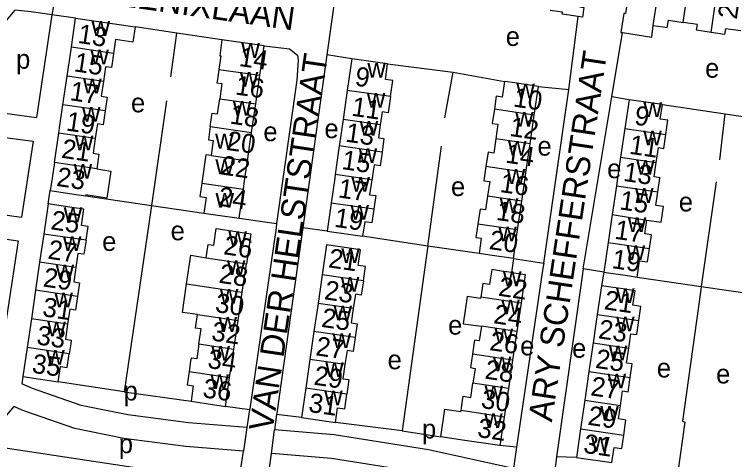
# Model space of a CAD drawing. Extents: x 163012 to 165277, y 382513 to 383987.
# Drawn here: x 163920.9 to 164071.5, y 382941.3 to 383034.2 of the extents above; entities that cross this region are included whole.
import ezdxf

# ---------------------------------------------------------------- set-up
doc = ezdxf.new("R2010")
doc.units = 0
for name, color, linetype in [('BLT_Basislijn', 7, 'Continuous'), ('BLT_Bebouwing', 7, 'Continuous'), ('BLT_Centroide', 7, 'Continuous'), ('BLT_Huisnummer', 7, 'Continuous'), ('BLT_Huisnummer_ tussenligend', 7, 'Continuous'), ('BLT_Onderverdeling_panden', 7, 'Continuous'), ('BLT_Straatnaam', 7, 'Continuous'), ('BLT_Vlakafsluiter', 7, 'Continuous')]:
    doc.layers.add(name, color=color, linetype=linetype)

msp = doc.modelspace()

# ---------------------------------------------------------------- linework, layer by layer
at = {"layer": 'BLT_Basislijn'}
for p, q in [((163933.72, 383033.43), (163928.78, 383034.15)), ((164036.78, 383018.52), (164038.76, 383033.78)), ((163954.91, 383030.33), (163946.16, 383031.61)), ((163953.66, 383021.2), (163954.91, 383030.33)), ((163964.32, 383028.95), (163954.91, 383030.33)), ((164045.79, 383016.99), (164048.02, 383030.43)), ((163986.21, 383025.76), (163981.2, 382989.66)), ((163991.46, 383024.98), (163986.21, 383025.76)), ((163998.93, 383023.9), (164012.67, 383022.18)), ((164010.93, 383012.61), (164012.67, 383022.18)), ((164012.67, 383022.18), (164023.35, 383020.25)), ((164030.48, 383019.21), (164036.78, 383018.52)), ((164031.56, 382982.31), (164036.78, 383018.52)), ((163952.71, 383016.16), (163949.61, 382994.31)), ((164039.84, 382981.1), (164045.79, 383016.99)), ((164049.39, 383016.42), (164045.79, 383016.99)), ((164056.37, 383015.39), (164069.46, 383013.45)), ((163915.9, 383013.98), (163925.56, 383012.72)), ((164068.4, 383003.83), (164069.46, 383013.45)), ((164069.46, 383013.45), (164081.1, 383011.71)), ((163915.17, 383009.03), (163924.82, 383007.78)), ((164007.33, 382985.82), (164010.19, 383006.73)), ((164067.6, 382999.24), (164064.49, 382977.41)), ((163928.01, 382994.65), (163928.43, 382997.43)), ((163935.85, 382996.34), (163949.61, 382994.31)), ((163949.61, 382994.31), (163960.52, 382992.74)), ((163912.83, 382993.19), (163922.44, 382991.91)), ((163967.92, 382991.65), (163975.74, 382990.58)), ((163986.27, 382988.97), (163981.2, 382989.66)), ((163912.1, 382988.25), (163921.69, 382986.96)), ((164007.33, 382985.82), (163993.71, 382987.89)), ((164018.04, 382984.28), (164007.33, 382985.82)), ((164025.22, 382983.23), (164024.81, 382980.34)), ((164025.22, 382983.23), (164031.56, 382982.31)), ((164044.12, 382980.42), (164039.84, 382981.1)), ((164044.12, 382980.42), (164043.65, 382977.56)), ((164051.08, 382979.39), (164064.49, 382977.41)), ((164064.49, 382977.41), (164075.82, 382975.74)), ((163922.7, 382958.59), (163922.48, 382957.11)), ((163943.88, 382955.44), (163930.09, 382957.5)), ((163943.88, 382955.44), (163957.85, 382953.43)), ((163970.07, 382951.64), (163965.04, 382952.37)), ((163970.07, 382951.64), (163969.53, 382947.96)), ((163975.74, 382950.65), (163975.31, 382947.48)), ((163980.93, 382950.04), (163975.74, 382950.65)), ((164001.96, 382947.28), (163988.05, 382949.01)), ((163969.53, 382947.96), (163968.8, 382943)), ((163974.64, 382942.52), (163975.31, 382947.48)), ((164001.96, 382947.28), (164010.03, 382946.03)), ((164025.87, 382943.82), (164022.36, 382944.19)), ((164025.87, 382943.82), (164025.23, 382939.42)), ((163968.18, 382938.94), (163968.8, 382943)), ((163974.01, 382938.04), (163974.64, 382942.52)), ((164034.21, 382941.83), (164033.72, 382937.87)), ((164038.39, 382941.7), (164034.21, 382941.83))]:
    msp.add_line(p, q, dxfattribs=at)
for points in [[(163988.64, 383043.13), (163986.29, 383026.31), (163986.21, 383025.76)], [(163928.78, 383034.15), (163924.42, 383034.78), (163920.99, 383035.12), (163918.78, 383032.49), (163918.5, 383031.62), (163915.9, 383013.98)], [(163928.78, 383034.15), (163925.56, 383012.72)], [(163973.1, 383027.69), (163978.4, 383027.01), (163980.11, 383025.72), (163980.23, 383024.68), (163979.98, 383020.47), (163975.74, 382990.58)], [(163924.82, 383007.78), (163922.44, 382991.91)], [(163949.61, 382994.31), (163949.47, 382993.33), (163943.88, 382955.44)], [(163975.74, 382990.58), (163975.61, 382989.65), (163970.11, 382951.89), (163970.07, 382951.64)], [(163981.2, 382989.66), (163981.07, 382988.73), (163975.77, 382950.92), (163975.74, 382950.65)], [(163921.69, 382986.96), (163918.94, 382968.59)], [(164007.33, 382985.82), (164007.21, 382984.96), (164001.96, 382947.28)], [(164031.56, 382982.31), (164031.41, 382981.22), (164025.87, 382943.82)], [(164039.84, 382981.1), (164039.58, 382979.58), (164034.21, 382941.83)], [(164064.49, 382977.41), (164064.32, 382976.22), (164060.57, 382949.27), (164061.03, 382949.04), (164059.62, 382938.6)], [(163969.53, 382947.96), (163957.3, 382948.96), (163944.65, 382950.6), (163934.91, 382952.57), (163924.74, 382956.08), (163922.48, 382957.11)], [(163968.8, 382943), (163956.77, 382943.99), (163943.83, 382945.66), (163933.59, 382947.74), (163922.89, 382951.43), (163920.84, 382952.36), (163914.82, 382945.41)], [(164025.23, 382939.42), (164007.45, 382943.3), (163987.8, 382946.46), (163975.31, 382947.48)], [(163918.6, 382943.79), (163957.28, 382937.97)], [(164024.5, 382934.46), (164006.52, 382938.39), (163987.2, 382941.49), (163974.64, 382942.52)]]:
    msp.add_lwpolyline(points, dxfattribs=at)
at = {"layer": 'BLT_Bebouwing'}
for p, q in [((163932.83, 383027.36), (163933.72, 383033.43)), ((163933.72, 383033.43), (163946.16, 383031.61)), ((163973.1, 383027.69), (163964.32, 383028.95)), ((163931.95, 383021.34), (163932.83, 383027.36)), ((163972.22, 383021.54), (163973.1, 383027.69)), ((163991.46, 383024.98), (163990.5, 383018.36)), ((163931.07, 383015.38), (163931.95, 383021.34)), ((163971.36, 383015.55), (163972.22, 383021.54)), ((164029.6, 383013.21), (164030.48, 383019.21)), ((163990.5, 383018.36), (163989.63, 383012.3)), ((164049.39, 383016.42), (164048.51, 383010.42)), ((163970.5, 383009.58), (163971.36, 383015.55)), ((164028.73, 383007.22), (164029.6, 383013.21)), ((164048.51, 383010.42), (164047.63, 383004.42)), ((163929.31, 383003.33), (163930.2, 383009.42)), ((164027.85, 383001.22), (164028.73, 383007.22)), ((163988.82, 383006.75), (163987.96, 383000.81)), ((164046.75, 382998.42), (164045.88, 382992.42)), ((163967.92, 382991.65), (163968.8, 382997.74)), ((164026.1, 382989.23), (164026.98, 382995.22)), ((163928.01, 382994.65), (163927.08, 382988.35)), ((163987.13, 382994.84), (163986.27, 382988.97)), ((164045.88, 382992.42), (164045.03, 382986.63)), ((164025.22, 382983.23), (164026.1, 382989.23)), ((163927.08, 382988.35), (163926.21, 382982.46)), ((164045.03, 382986.63), (164044.12, 382980.42)), ((163926.21, 382982.46), (163925.36, 382976.62)), ((163968.55, 382976.23), (163969.42, 382982.17)), ((163985.26, 382979.84), (163984.39, 382973.87)), ((164043.65, 382977.56), (164042.77, 382971.59)), ((163925.36, 382976.62), (163924.47, 382970.64)), ((163967.68, 382970.3), (163968.55, 382976.23)), ((163984.39, 382973.87), (163983.54, 382967.99)), ((164026.83, 382973.96), (164025.94, 382968)), ((164042.77, 382971.59), (164041.9, 382965.62)), ((163924.47, 382970.64), (163923.59, 382964.64)), ((163966.8, 382964.34), (163967.68, 382970.3)), ((163983.54, 382967.99), (163982.69, 382962.16)), ((164025.94, 382968), (164025.05, 382962.05)), ((164041.9, 382965.62), (164041.02, 382959.65)), ((163923.59, 382964.64), (163922.7, 382958.59)), ((163965.92, 382958.41), (163966.8, 382964.34)), ((163982.69, 382962.16), (163981.82, 382956.16)), ((164025.05, 382962.05), (164024.17, 382956.09)), ((164041.02, 382959.65), (164040.14, 382953.68)), ((163922.7, 382958.59), (163930.09, 382957.5)), ((163965.04, 382952.37), (163965.92, 382958.41)), ((163981.82, 382956.16), (163980.93, 382950.04)), ((164024.17, 382956.09), (164023.28, 382950.14)), ((163957.85, 382953.43), (163965.04, 382952.37)), ((164040.14, 382953.68), (164039.27, 382947.71)), ((163980.93, 382950.04), (163988.05, 382949.01)), ((164023.28, 382950.14), (164022.36, 382944.19)), ((164039.27, 382947.71), (164038.39, 382941.7)), ((164038.39, 382941.7), (164045.81, 382940.64))]:
    msp.add_line(p, q, dxfattribs=at)
for points in [[(164040.16, 383043.22), (164039.09, 383035.8), (164039.95, 383035.67), (164039.65, 383033.65), (164038.76, 383033.78)], [(164049.79, 383041.81), (164048.68, 383034.4), (164048.3, 383034.45), (164047.7, 383030.48), (164048.02, 383030.43)], [(164038.76, 383033.78), (164035.42, 383034.26), (164035.48, 383034.7), (164032.9, 383035.08)], [(164054.45, 383031.92), (164056.52, 383031.61), (164057.4, 383031.47), (164057.63, 383033.02), (164060.7, 383032.56)], [(164066.54, 383030.45), (164063.52, 383030.91), (164063.7, 383032.11), (164060.7, 383032.56)], [(163946.16, 383031.61), (163945.69, 383028.43), (163942.07, 383029), (163941.64, 383026.06)], [(164048.02, 383030.43), (164054.13, 383029.51), (164054.45, 383031.92)], [(164072.74, 383030.77), (164069.55, 383031.24), (164069.37, 383030.03), (164066.54, 383030.45)], [(163964.32, 383028.95), (163963.84, 383025.61), (163964.07, 383025.57), (163963.66, 383022.76)], [(163941.64, 383026.06), (163941.35, 383024.05), (163941.21, 383023.12), (163939.98, 383023.31), (163939.53, 383020.23)], [(163998.93, 383023.9), (163996.41, 383024.26), (163991.46, 383024.98)], [(163999.51, 383017.06), (164000, 383020.41), (163998.46, 383020.64), (163998.93, 383023.9)], [(163963.66, 383022.76), (163963.36, 383020.62), (163963.26, 383019.96), (163964.31, 383019.81), (163963.85, 383016.62)], [(163939.53, 383020.23), (163939.08, 383017.16), (163940.31, 383016.98), (163939.88, 383014.08)], [(164023.35, 383020.25), (164022.87, 383016.96), (164021.64, 383017.14), (164021.25, 383014.43)], [(164030.48, 383019.21), (164025.53, 383019.93), (164023.35, 383020.25)], [(163961.87, 383010.82), (163962.27, 383013.6), (163963.39, 383013.44), (163963.85, 383016.62)], [(163999.51, 383017.06), (163999.03, 383013.7), (163997.8, 383013.88), (163997.4, 383011.17)], [(164056.37, 383015.39), (164054.34, 383015.69), (164049.39, 383016.42)], [(163930.2, 383009.42), (163930.37, 383010.57), (163931.07, 383015.38)], [(164021.25, 383014.43), (164020.81, 383011.46), (164022, 383011.29), (164021.56, 383008.26)], [(164057.08, 383009.16), (164057.51, 383012.13), (164055.93, 383012.36), (164056.37, 383015.39)], [(163939.88, 383014.08), (163939.46, 383011.19), (163938.27, 383011.36), (163938.09, 383010.12), (163937.83, 383008.3)], [(163989.63, 383012.3), (163988.87, 383007.1), (163988.82, 383006.75)], [(163961.87, 383010.82), (163961.47, 383008.05), (163962.49, 383007.9), (163962.03, 383004.74)], [(163997.4, 383011.17), (163997.01, 383008.46), (163998.18, 383008.29), (163997.93, 383006.56), (163997.77, 383005.46)], [(163969.65, 383003.65), (163970.3, 383008.2), (163970.5, 383009.58)], [(164055.08, 383003.33), (164055.53, 383006.41), (164056.65, 383006.25), (164057.08, 383009.16)], [(163937.83, 383008.3), (163937.38, 383005.24), (163938.58, 383005.07), (163938.13, 383001.96)], [(164021.56, 383008.26), (164021.12, 383005.26), (164019.94, 383005.43), (164019.49, 383002.44)], [(163997.77, 383005.46), (163997.36, 383002.63), (163996.14, 383002.8), (163995.68, 383000), (163995.64, 382999.69)], [(163962.03, 383004.74), (163960.97, 383004.9), (163960.11, 382998.99)], [(164047.63, 383004.42), (164046.99, 383000), (164046.75, 382998.42)], [(163929.31, 383003.33), (163928.82, 383000), (163928.43, 382997.43)], [(163968.8, 382997.74), (163969.12, 383000), (163969.65, 383003.65)], [(164019.49, 383002.44), (164019.12, 383000), (164019.05, 382999.5), (164020.28, 382999.32), (164019.83, 382996.27)], [(164055.41, 382997.15), (164055.86, 383000), (164055.87, 383000.11), (164054.63, 383000.29), (164055.08, 383003.33)], [(163938.13, 383001.96), (163941.07, 383001.52), (163940.22, 382995.86), (163935.88, 382996.58), (163935.85, 382996.34)], [(164026.98, 382995.22), (164027.68, 383000), (164027.85, 383001.22)], [(163987.96, 383000.81), (163987.88, 383000), (163987.13, 382994.84)], [(163995.64, 382999.69), (163995.18, 382996.57), (163996.45, 382996.39), (163996.03, 382993.54)], [(163960.11, 382998.99), (163959.67, 382996.17), (163961, 382995.97), (163960.52, 382992.74)], [(163928.43, 382997.43), (163933.37, 382996.7), (163935.85, 382996.34)], [(164053.14, 382991.29), (164056.12, 382990.86), (164056.6, 382994.11), (164054.98, 382994.35), (164055.41, 382997.15)], [(164019.83, 382996.27), (164019.41, 382993.39), (164018.25, 382993.56), (164017.8, 382990.44)], [(163935.9, 382987.05), (163936.33, 382989.95), (163934.93, 382990.15), (163935.43, 382993.56), (163932.96, 382993.92), (163928.01, 382994.65)], [(163996.03, 382993.54), (163995.62, 382990.7), (163994.15, 382990.91), (163993.71, 382987.89)], [(163960.52, 382992.74), (163962.97, 382992.38), (163967.92, 382991.65)], [(164017.8, 382990.44), (164017.39, 382987.66), (164018.51, 382987.5), (164018.04, 382984.28)], [(164053.67, 382985.37), (164054.08, 382988.21), (164052.71, 382988.41), (164053.14, 382991.29)], [(163960.99, 382983.41), (163961.4, 382986.19), (163962.59, 382986.02), (163963.1, 382989.49), (163965.4, 382989.16), (163970.34, 382988.43), (163969.42, 382982.17)], [(163986.27, 382988.97), (163991.22, 382988.25), (163993.71, 382987.89)], [(163935.9, 382987.05), (163935.47, 382984.15), (163934.2, 382984.33), (163933.76, 382981.35)], [(163993.87, 382978.58), (163994.31, 382981.55), (163992.81, 382981.77), (163993.29, 382985.07), (163986.18, 382986.11), (163985.26, 382979.84)], [(164051.08, 382979.39), (164051.58, 382982.77), (164053.25, 382982.53), (164053.67, 382985.37)], [(163956.93, 382977.96), (163957.81, 382983.93), (163960.99, 382983.41)], [(164025.22, 382983.23), (164020.27, 382983.96), (164018.04, 382984.28)], [(163933.76, 382981.35), (163933.33, 382978.37), (163934.53, 382978.19), (163934.11, 382975.33)], [(164024.81, 382980.34), (164022.77, 382980.64), (164020.71, 382980.95), (164020.24, 382977.81), (164018.85, 382978.02), (164018.43, 382975.21)], [(164024.81, 382980.34), (164027.72, 382979.91), (164026.83, 382973.96)], [(164044.12, 382980.42), (164049.06, 382979.69), (164051.08, 382979.39)], [(163993.87, 382978.58), (163993.44, 382975.62), (163992.2, 382975.8), (163991.76, 382972.79)], [(163959.22, 382971.55), (163956.06, 382972), (163956.93, 382977.96)], [(164051.46, 382970.31), (164051.89, 382973.23), (164050.21, 382973.48), (164050.66, 382976.53), (164048.6, 382976.83), (164043.65, 382977.56)], [(163934.11, 382975.33), (163933.69, 382972.48), (163932.52, 382972.65), (163932.06, 382969.53)], [(164018.43, 382975.21), (164018.38, 382974.89), (164015.58, 382975.3), (164014.73, 382969.6), (164018.54, 382969.1)], [(163991.76, 382972.79), (163991.32, 382969.79), (163992.55, 382969.61), (163992.14, 382966.74)], [(163959.51, 382965.42), (163959.97, 382968.56), (163958.81, 382968.73), (163959.22, 382971.55)], [(163932.06, 382969.53), (163931.61, 382966.4), (163932.82, 382966.22), (163932.71, 382965.42), (163932.4, 382963.34)], [(164049.35, 382964.52), (164049.8, 382967.53), (164051.03, 382967.35), (164051.46, 382970.31)], [(164018.54, 382969.1), (164018.09, 382966.04), (164017.1, 382966.19), (164016.67, 382963.3)], [(163992.14, 382966.74), (163991.72, 382963.86), (163990.45, 382964.05), (163990.02, 382961.09)], [(163959.51, 382965.42), (163959.04, 382962.27), (163957.85, 382962.45), (163957.76, 382961.81), (163957.44, 382959.66)], [(163930.09, 382957.5), (163930.56, 382960.68), (163931.98, 382960.47), (163932.4, 382963.34)], [(164016.67, 382963.3), (164016.24, 382960.46), (164017.25, 382960.31), (164016.78, 382957.19)], [(164049.65, 382958.38), (164050.07, 382961.24), (164048.9, 382961.42), (164049.35, 382964.52)], [(163990.02, 382961.09), (163989.59, 382958.14), (163990.86, 382957.96), (163990.42, 382954.9)], [(163957.44, 382959.66), (163957.03, 382956.87), (163958.32, 382956.68), (163957.85, 382953.43)], [(164047.58, 382952.59), (164048.02, 382955.59), (164049.22, 382955.42), (164049.65, 382958.38)], [(164014.28, 382951.48), (164014.6, 382953.61), (164014.73, 382954.5), (164016.35, 382954.26), (164016.78, 382957.19)], [(163988.05, 382949.01), (163988.49, 382952.07), (163989.97, 382951.85), (163990.42, 382954.9)], [(164010.03, 382946.03), (164010.89, 382951.81), (164014.25, 382951.31), (164014.28, 382951.48)], [(164048.28, 382946.38), (164048.59, 382948.49), (164048.75, 382949.52), (164047.16, 382949.76), (164047.58, 382952.59)], [(164022.36, 382944.19), (164015.11, 382945.27), (164010.03, 382946.03)], [(164045.81, 382940.64), (164046.27, 382943.78), (164047.86, 382943.55), (164048.28, 382946.38)]]:
    msp.add_lwpolyline(points, dxfattribs=at)
at = {"layer": 'BLT_Onderverdeling_panden'}
for p, q in [((164054.45, 383031.92), (164055.8, 383040.91)), ((164060.7, 383032.56), (164061.82, 383040.01)), ((164066.54, 383030.45), (164067.84, 383039.11)), ((163941.64, 383026.06), (163932.83, 383027.36)), ((163963.66, 383022.76), (163972.22, 383021.54)), ((163939.53, 383020.23), (163931.95, 383021.34)), ((163999.51, 383017.06), (163990.5, 383018.36)), ((163963.85, 383016.62), (163971.36, 383015.55)), ((163939.88, 383014.08), (163931.07, 383015.38)), ((164029.6, 383013.21), (164021.25, 383014.43)), ((163997.4, 383011.17), (163989.63, 383012.3)), ((163961.87, 383010.82), (163970.5, 383009.58)), ((164048.51, 383010.42), (164057.08, 383009.16)), ((163937.83, 383008.3), (163930.2, 383009.42)), ((164028.73, 383007.22), (164021.56, 383008.26)), ((163997.77, 383005.46), (163988.82, 383006.75)), ((163962.03, 383004.74), (163969.65, 383003.65)), ((164047.63, 383004.42), (164055.08, 383003.33)), ((163938.13, 383001.96), (163929.31, 383003.33)), ((164027.85, 383001.22), (164019.49, 383002.44)), ((163995.64, 382999.69), (163987.96, 383000.81)), ((163960.11, 382998.99), (163968.8, 382997.74)), ((164046.75, 382998.42), (164055.41, 382997.15)), ((164026.98, 382995.22), (164019.83, 382996.27)), ((163996.03, 382993.54), (163987.13, 382994.84)), ((164045.88, 382992.42), (164053.14, 382991.29)), ((164026.1, 382989.23), (164017.8, 382990.44)), ((163935.9, 382987.05), (163927.08, 382988.35)), ((164045.03, 382986.63), (164053.67, 382985.37)), ((163960.99, 382983.41), (163969.42, 382982.17)), ((163933.76, 382981.35), (163926.21, 382982.46)), ((163993.87, 382978.58), (163985.26, 382979.84)), ((163956.93, 382977.96), (163968.55, 382976.23)), ((163934.11, 382975.33), (163925.36, 382976.62)), ((163991.76, 382972.79), (163984.39, 382973.87)), ((164026.83, 382973.96), (164018.43, 382975.21)), ((163959.22, 382971.55), (163967.68, 382970.3)), ((164042.77, 382971.59), (164051.46, 382970.31)), ((163932.06, 382969.53), (163924.47, 382970.64)), ((163992.14, 382966.74), (163983.54, 382967.99)), ((164025.94, 382968), (164018.54, 382969.1)), ((163959.51, 382965.42), (163966.8, 382964.34)), ((164041.9, 382965.62), (164049.35, 382964.52)), ((163932.4, 382963.34), (163923.59, 382964.64)), ((164025.05, 382962.05), (164016.67, 382963.3)), ((163990.02, 382961.09), (163982.69, 382962.16)), ((163957.44, 382959.66), (163965.92, 382958.41)), ((164041.02, 382959.65), (164049.65, 382958.38)), ((163990.42, 382954.9), (163981.82, 382956.16)), ((164024.17, 382956.09), (164016.78, 382957.19)), ((164040.14, 382953.68), (164047.58, 382952.59)), ((164023.28, 382950.14), (164014.28, 382951.48)), ((164039.27, 382947.71), (164048.28, 382946.38))]:
    msp.add_line(p, q, dxfattribs=at)
at = {"layer": 'BLT_Vlakafsluiter'}
msp.add_line((163930.98, 383046.09), (163928.78, 383034.15), dxfattribs=at)

# ---------------------------------------------------------------- texts
at = {"layer": 'BLT_Centroide'}
for s, p in [('w', (163937.05, 383029.75)), ('e', (164023.63, 383027.65)), ('w', (163968.37, 383025.16)), ('w', (163936.81, 383023.78)), ('p', (163921.28, 383022.89)), ('w', (163994.7, 383021.03)), ('e', (164065.3, 383021.02)), ('w', (163968.05, 383019.16)), ('w', (163935.29, 383017.72)), ('w', (164025.85, 383016.72)), ('w', (163994.59, 383014.75)), ('e', (163945.3, 383013.78)), ('w', (163966.59, 383013.09)), ('w', (163935.05, 383011.84)), ('w', (164052.42, 383012.78)), ('w', (164025.59, 383010.81)), ('e', (163985.73, 383008.39)), ('w', (163993.1, 383008.88)), ('e', (163972.96, 383007.77)), ('w', (164052.38, 383006.88)), ('w', (163933.57, 383005.84)), ('w', (163962.89, 383006.22)), ('w', (164024.1, 383004.75)), ('e', (164030.26, 383004.74)), ('w', (163992.88, 383003.22)), ('w', (163962.95, 383000.86)), ('w', (163933.32, 382999.94)), ('e', (164044.82, 383000.02)), ('w', (164050.9, 383000.78)), ('w', (164023.85, 382998.84)), ('w', (163991.37, 382997.19)), ('e', (164012.18, 382996.3)), ('w', (164050.65, 382994.88)), ('w', (163962.98, 382993.84)), ('w', (164022.38, 382992.75)), ('e', (164059.79, 382993.09)), ('w', (163931.24, 382990.84)), ('w', (163991.17, 382991.38)), ('w', (164049.14, 382988.78)), ('e', (163953.58, 382987.06)), ('w', (163965.66, 382985.84)), ('w', (164022.08, 382986.84)), ('w', (163931.07, 382984.84)), ('e', (163939.27, 382984.84)), ('w', (164048.89, 382982.91)), ('w', (163989.26, 382982.34)), ('w', (163965.35, 382979.81)), ('w', (163929.55, 382978.91)), ('w', (164023.05, 382977.47)), ('w', (163989.15, 382976.31)), ('w', (163963.87, 382973.81)), ('w', (164046.7, 382973.94)), ('w', (163929.3, 382973.06)), ('w', (164022.7, 382971.59)), ('w', (163987.63, 382970.31)), ('w', (163963.6, 382967.94)), ('w', (164046.7, 382968.06)), ('w', (163927.81, 382967)), ('e', (164011.58, 382967.36)), ('w', (164021.3, 382965.56)), ('w', (163987.42, 382964.53)), ('w', (163962.1, 382961.91)), ('e', (164026.64, 382963.03)), ('e', (164037.49, 382962.53)), ('w', (164045.17, 382962)), ('w', (163927.56, 382961.06)), ('e', (163998.93, 382960.12)), ('w', (164020.93, 382959.69)), ('w', (163985.9, 382958.53)), ('e', (164055.21, 382958.41)), ('e', (164067.59, 382957.16)), ('w', (163961.9, 382956)), ('w', (164044.91, 382956.12)), ('p', (163943.74, 382953.6)), ('w', (164019.2, 382953.66)), ('w', (163985.69, 382952.59)), ('w', (164043.39, 382949.39)), ('w', (164019.13, 382947.84)), ('p', (164006.12, 382945.67)), ('p', (163942.75, 382942.59)), ('w', (164041.46, 382942.92))]:
    msp.add_text(s, height=4, dxfattribs=at).set_placement(p)
at = {"layer": 'BLT_Huisnummer'}
for s, rotation, p in [('25', 81.4715, (164071.89, 383033.07)), ('13', 351.6615, (163934.04, 383028.3)), ('14', 351.8336, (163967.74, 383023.47)), ('9', 351.7586, (163991.95, 383019.4)), ('17', 351.6534, (163932.37, 383016.34)), ('10', 351.6762, (164025.06, 383015.01)), ('18', 351.8236, (163965.81, 383011.46)), ('9', 351.664, (164050.38, 383011.25)), ('13', 351.7659, (163989.99, 383007.69)), ('14', 351.6734, (164023.44, 383003.3)), ('13', 351.6652, (164048.05, 382999.48)), ('23', 351.6284, (163929.57, 382998.44)), ('24', 351.6268, (163963.33, 382994.31)), ('19', 351.706, (163987.65, 382989.9)), ('25', 351.6254, (163928.37, 382989.38)), ('20', 351.6578, (164020, 382985.25)), ('26', 351.5193, (163964.5, 382984.17)), ('21', 351.7209, (163986.41, 382981.43)), ('19', 351.6511, (164045.65, 382981.27)), ('29', 351.6587, (163926.79, 382977.43)), ('22', 351.52, (164021.93, 382975.51)), ('30', 351.6357, (163962.74, 382972.11)), ('21', 351.6505, (164044.05, 382972.68)), ('25', 351.7141, (163984.95, 382969)), ('26', 351.5171, (164020.1, 382964.15)), ('35', 351.6236, (163924.43, 382959.43)), ('25', 351.6477, (164042.22, 382960.44)), ('36', 351.6213, (163960.14, 382954.29)), ('31', 351.7145, (163982.25, 382951.24)), ('32', 351.5112, (164017.55, 382946.01)), ('31', 351.6441, (164039.72, 382942.7))]:
    msp.add_text(s, height=4, rotation=rotation, dxfattribs=at).set_placement(p)
at = {"layer": 'BLT_Huisnummer_ tussenligend'}
for s, rotation, p in [('15', 351.6615, (163933.25, 383022.36)), ('16', 351.8336, (163966.95, 383017.53)), ('11', 351.7586, (163991.25, 383013.1)), ('19', 351.6534, (163931.59, 383010.01)), ('12', 351.6762, (164024.28, 383008.87)), ('20', 351.8236, (163965.12, 383005.96)), ('11', 351.664, (164049.29, 383005.15)), ('21', 351.6284, (163930.61, 383004.32)), ('15', 351.7659, (163989.2, 383001.95)), ('22', 351.6268, (163963.94, 383000.84)), ('16', 351.6734, (164022.26, 382997.16)), ('17', 351.706, (163988.44, 382996.04)), ('15', 351.6652, (164047.26, 382993.54)), ('18', 351.6578, (164021.48, 382991.34)), ('17', 351.6511, (164046.23, 382987.4)), ('27', 351.6254, (163927.76, 382983.25)), ('28', 351.5193, (163963.52, 382978.22)), ('23', 351.7209, (163985.57, 382974.76)), ('31', 351.6587, (163926.65, 382971.22)), ('24', 351.52, (164020.93, 382969.77)), ('32', 351.6357, (163961.96, 382966.16)), ('23', 351.6505, (164042.82, 382966.61)), ('33', 351.6587, (163925.41, 382965.35)), ('27', 351.7141, (163983.75, 382963.06)), ('34', 351.6357, (163961.16, 382960.42)), ('28', 351.5171, (164019.11, 382958.2)), ('29', 351.7141, (163983.36, 382956.92)), ('27', 351.6477, (164041.22, 382954.7)), ('30', 351.5171, (164018.32, 382952.07)), ('29', 351.6477, (164040.63, 382948.56))]:
    msp.add_text(s, height=4, rotation=rotation, dxfattribs=at).set_placement(p)
at = {"layer": 'BLT_Straatnaam'}
for s, height, rotation, p in [('JAN WEENIXLAAN', 5, 351.9305, (163921.44, 383039.07)), ('ARY SCHEFFERSTRAAT', 5, 81.4856, (164033.26, 382948.99)), ('VAN DER HELSTSTRAAT', 4.9999, 81.6106, (163974.87, 382946.96))]:
    msp.add_text(s, height=height, rotation=rotation, dxfattribs=at).set_placement(p)

doc.saveas('drawing.dxf')
